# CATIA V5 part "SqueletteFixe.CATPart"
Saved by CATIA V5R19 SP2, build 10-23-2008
Part number: SqueletteFixe
Publications: "FixA", "FixD", "FixG"
Bounding box of the stored display mesh (mm): x -20 to 20, y 0 to 60, z 0 to 171.213
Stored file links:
  D:\France\IFMA\IAO\Projet\SqueletteFixe.CATPart
  D:\France\IFMA\IAO\Projet\pruangdaja_CAO.CATProduct
  D:\France\IFMA\IAO\Projet\SqueletteAB.CATPart
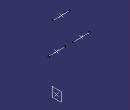
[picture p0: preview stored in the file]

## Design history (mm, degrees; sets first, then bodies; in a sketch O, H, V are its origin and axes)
Set1
  Point1: linked copy from another document
  Plane1: linked copy from another document
  Point2: linked copy from another document
  Line1: linked copy from another document
  Point3: linked copy from another document
  Line2: linked copy from another document
  Point4: linked copy from another document
  Line3: linked copy from another document
Set2
  Point5: (0, 0, 0), relative to Point2
  Point6: (0, 0, 0), relative to Point3
  Point7: (0, 0, 0), relative to Point4
Body1 (main body)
